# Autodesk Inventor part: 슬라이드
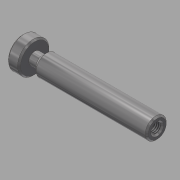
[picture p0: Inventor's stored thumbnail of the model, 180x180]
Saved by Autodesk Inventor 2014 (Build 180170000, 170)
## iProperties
Created: 2015-12
Part Number: 슬라이드
Document SubType Name: Modeling
Designer: mdu
Density: 8.08 g/cm^3
Material: 강철, 탄소
Appearance: 반연마
Mass: 114.493 g
Surface Area: 49.8963 cm^2
Volume: 14.17 cm^3
Author: mdu
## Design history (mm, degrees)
sketch "스케치1"
  geometry: L1 (-45, 0)-(45, 0); L2 (-45, 0)-(-45, 10.5); L3 (-45, 10.5)-(-37, 10.5); L4 (-37, 10.5)-(-37, 4); L5 (-37, 4)-(-32, 4); L6 (-32, 4)-(-29, 7); L7 (-29, 7)-(45, 7); L8 (45, 7)-(45, 0); 2 further points
  constraints: 16 end point, 4 parallel, 2 perpendicular, 1 coincident, 1 horizontal, 1 midpoint
  dimensions: "d0" = 90 distance of L1.start L1.end; "d1" = 21 diameter of L3 L1; "d2" = 14 diameter of L7 L1; "d3" = 8 diameter of L5 L1; "d4" = 8 distance of L2.end L3.end; "d5" = 5 distance of L4.end L5.end; "d6" = 135 deg angle of L6 L5
revolve "회전1" sketch "스케치1" stored, may be unused: angle "d7" = 90 deg
chamfer "모따기1" distance "d8" = 1; stored, may be unused: second distance "d9" = 2, angle "d10" = 45 deg
hole "구멍1" diameter "d13" = 6.647; stored, may be unused: countersink angle "d17" = 90 deg, drill point angle "d19" = 118 deg; dims "d11" = 10, "d12" = 10, "d14" = 9, "d15" = 4, "d16" = 2, "d18" = 12
chamfer "모따기2" distance "d20" = 1; stored, may be unused: second distance "d21" = 2, angle "d22" = 45 deg
node "솔리드1"
